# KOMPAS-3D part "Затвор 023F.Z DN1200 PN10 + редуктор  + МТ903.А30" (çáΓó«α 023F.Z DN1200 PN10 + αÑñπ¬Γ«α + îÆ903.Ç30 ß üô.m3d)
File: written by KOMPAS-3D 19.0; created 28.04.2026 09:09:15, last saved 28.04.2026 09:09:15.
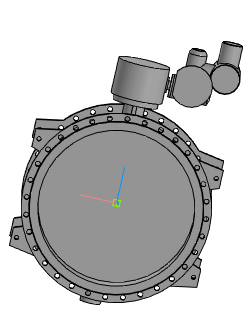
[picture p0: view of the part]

Document properties: Полное имя файла: ..\..\Затвор 023F.Z DN400-DN1600 + редуктор + МТ903\Затвор 023F.Z DN1200 PN10 + редуктор + МТ903.А30 с БУ.a3d

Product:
- Part/product: Затвор 023F.Z DN1200 PN10 + редуктор  + МТ903.А30
    Масса: 2346.84

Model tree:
1. Операция без истории:1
